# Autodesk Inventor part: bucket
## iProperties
Author: Vincent Molino
Shininess: 9.0
Angle Display Precision: 2
Document Length Units: 11272
Document Angle Units: 11286
Document Time Units: 11279
Document Mass Units: 11290
Document Length Units Precision: 3
Document Angle Units Precision: 2
Compacted: True
PropertySet Name: _Private Model Information
Created: 2002-05
Part Number: bucket
Document SubType Name: Modeling
Designer: Vincent Molino
Control State: 0
Master: False
Checked Out: False
PropertySet Name: Design Tracking Control
Density: 0.0
Volumn: 0.0
Area: 0.0
PropertySet Name: Model Information
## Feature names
1. Extrusion1
2. Extrusion2
3. Extrusion3
4. Extrusion4
5. Fillet1
6. Fillet2
7. Extrusion5
8. Extrusion6
9. Extrusion7
